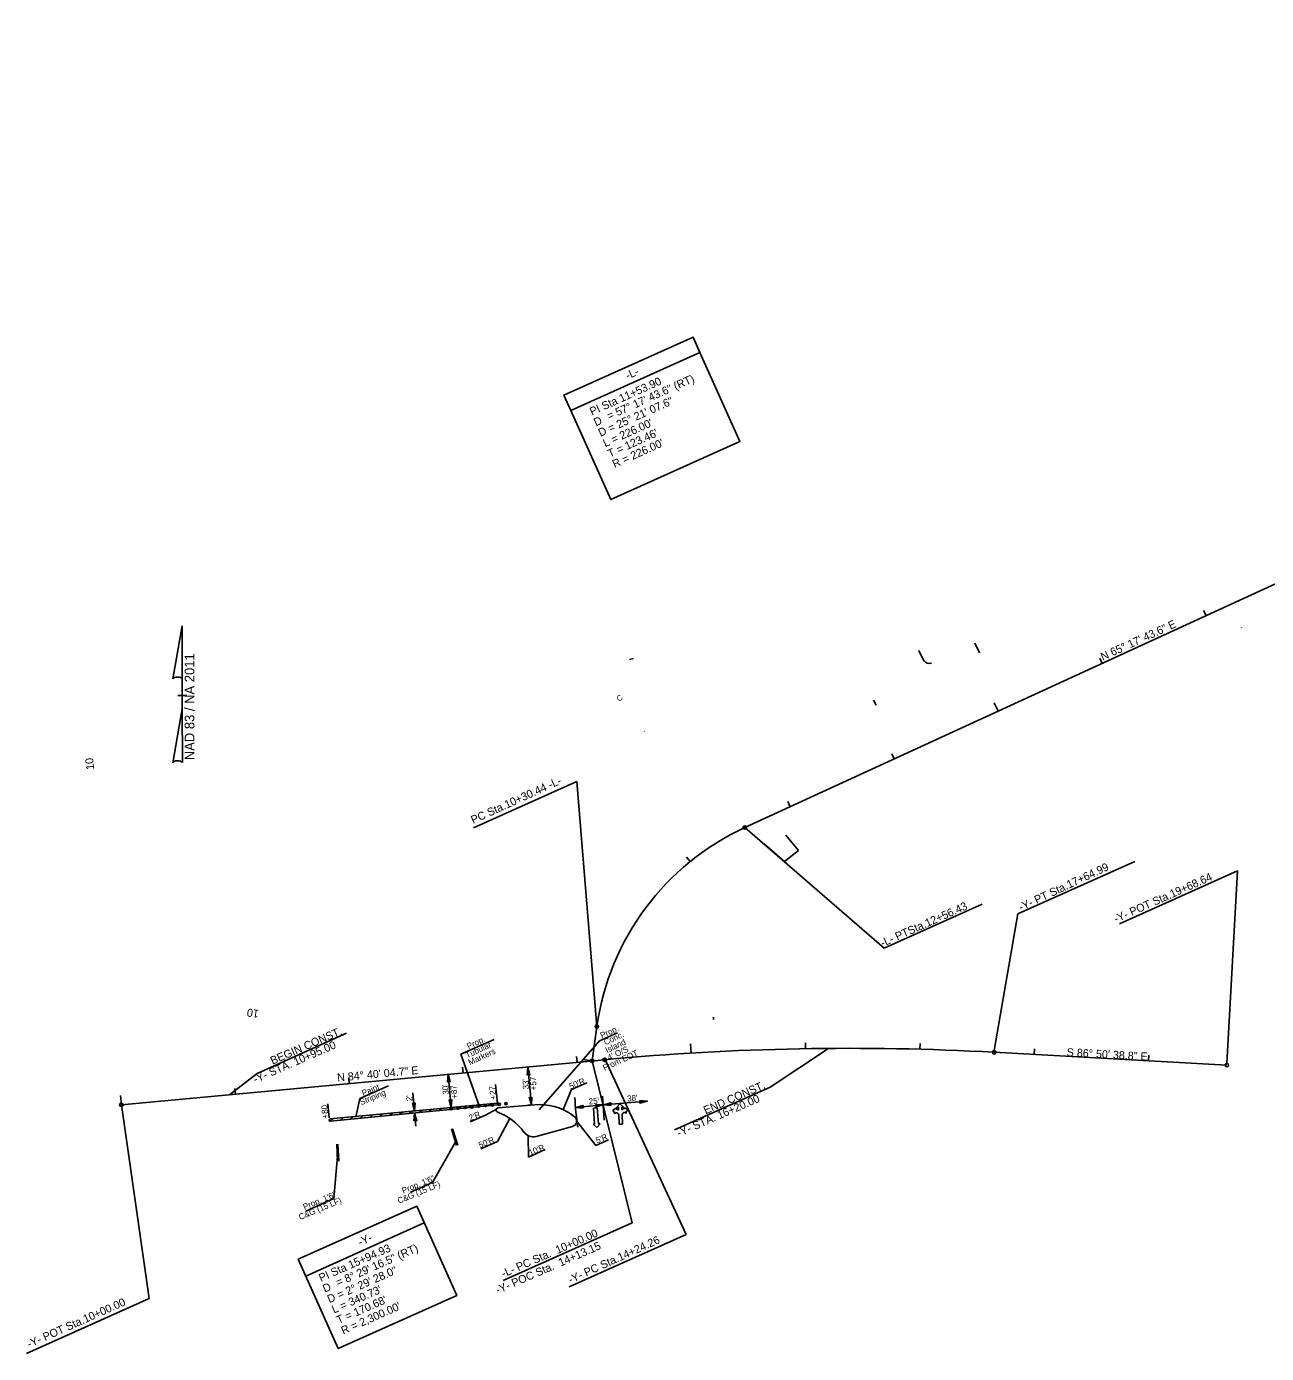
# Model space of a CAD drawing. Extents: x 549330 to 561351, y 501561 to 509732.
# Drawn here: x 553991 to 555075, y 502823 to 503983 of the extents above; entities that cross this region are included whole.
import ezdxf

# ---------------------------------------------------------------- set-up
doc = ezdxf.new("R2010")
doc.units = 0
for name, color, linetype in [('Old_Level_10', 7, 'Continuous'), ('Prop CMT Slope Fill', 7, 'Continuous'), ('Prop Conc 1ft 6in Curb and Gutter', 7, 'Continuous'), ('Prop Conc 5in Monolithic Surface Mount Island', 7, 'Continuous'), ('Prop Dimension', 7, 'Continuous'), ('Prop Drainage Structure Drop Inlet Grate 2 Narrow Slots and Flat Grates 840 29 TB CELL', 7, 'Continuous'), ('Prop Drainage Structure Pipe Alternate 15in', 7, 'Continuous'), ('Prop Drainage Structure Plot Symbol 50 Scale', 7, 'Continuous'), ('Prop Drainage Structure Tops and Inverts LABEL', 7, 'Continuous'), ('Prop Horizontal Alignment', 7, 'Continuous'), ('Prop Horizontal Alignment Station Label', 7, 'Continuous'), ('Prop Paint Stripe', 7, 'Continuous'), ('Prop Plan Preparation Table Ditch Data CELL', 7, 'Continuous'), ('Prop Shade Light', 7, 'Continuous'), ('Prop Shade Medium', 7, 'Continuous'), ('Prop SS Cut Text', 7, 'Continuous'), ('Scratch_Level_5', 7, 'Continuous'), ('Sheet Cutting Line CELL', 7, 'Continuous'), ('Sheet Sticker Incomplete CELL', 7, 'Continuous'), ('Sheet Title CELL', 7, 'Continuous'), ('Typical Terminator CELL', 7, 'Continuous')]:
    doc.layers.add(name, color=color, linetype=linetype)

msp = doc.modelspace()

# ---------------------------------------------------------------- linework, layer by layer
at = {"layer": 'Old_Level_10'}
for centre in [(554374.6, 503038.2), (554380.6, 503038.7), (554386.5, 503039.3), (554392.5, 503039.9), (554398.5, 503040.4), (554404.5, 503041), (554410.4, 503041.5), (554362.6, 503037.1), (554368.6, 503037.6)]:
    msp.add_circle(centre, 1, dxfattribs=at)
at = {"layer": 'Prop CMT Slope Fill'}
for p, q in [((554518.3, 503429.8), (554521.8, 503430.7)), ((554531.1, 503367.3), (554531.5, 503366.8))]:
    msp.add_line(p, q, dxfattribs=at)
at = {"layer": 'Prop Conc 1ft 6in Curb and Gutter'}
for p, q in [((554362.8, 503019.5), (554367.3, 503004.9)), ((554363.8, 503019.6), (554368.3, 503005.1)), ((554262.6, 503006.1), (554263.2, 502991.1)), ((554263.6, 503006.2), (554264.2, 502991.1))]:
    msp.add_line(p, q, dxfattribs=at)
at = {"layer": 'Prop Conc 5in Monolithic Surface Mount Island'}
for p, q in [((554403, 503040.8), (554403, 503040.8)), ((554403, 503040.8), (554403, 503040.8)), ((554403, 503040.8), (554403, 503040.8)), ((554403, 503040.8), (554403, 503040.8)), ((554403, 503040.8), (554403, 503040.8)), ((554403, 503040.8), (554403, 503040.8)), ((554403.7, 503037.9), (554435.2, 503040.6)), ((554468.1, 503031.8), (554470.1, 503030.4)), ((554436.9, 503012.9), (554468.6, 503021.5)), ((554436.9, 503012.9), (554468.6, 503021.5))]:
    msp.add_line(p, q, dxfattribs=at)
msp.add_lwpolyline([(554360.7, 503037.2), (554360.7, 503037.2)], dxfattribs=at)
for centre, radius, start, end in [((554439.5, 502990.8), 50, 55.0742, 94.9315), ((554403.9, 503035.9), 2, 94.9315, 249.5992), ((554385.7, 502987.2), 50, 36.037, 69.5992), ((554467.2, 503026.3), 5, 285.283, 55.0742), ((554434.3, 503022.5), 10, 216.037, 285.283)]:
    msp.add_arc(centre, radius, start, end, dxfattribs=at)
at = {"layer": 'Prop Dimension'}
for points in [[(554467, 503647.7), (554579.9, 503698.4), (554573.9, 503711.8), (554461, 503661.1)], [(554467, 503647.7), (554579.9, 503698.4), (554614.9, 503620.4), (554502, 503569.7)], [(554228.8, 502905.4), (554332.4, 502951.8), (554367.4, 502873.8), (554263.9, 502827.4)]]:
    msp.add_lwpolyline(points, close=True, dxfattribs=at)
at = {"layer": 'Prop Drainage Structure Drop Inlet Grate 2 Narrow Slots and Flat Grates 840 29 TB CELL'}
for points in [[(554359.3, 503060.4), (554359.8, 503067.3), (554361.6, 503060.6), (554360.4, 503061.4)], [(554429, 503066.4), (554429.5, 503073.2), (554431.4, 503066.6), (554430.1, 503067.3)], [(554331, 503042.1), (554330.4, 503035.3), (554328.6, 503041.9), (554329.9, 503041.2)], [(554363.1, 503045), (554362.5, 503038.2), (554360.7, 503044.8), (554362, 503044.1)], [(554433, 503047.3), (554432.6, 503040.4), (554430.7, 503047), (554431.9, 503046.3)], [(554478, 503037.6), (554471.2, 503038.2), (554477.8, 503040), (554477.1, 503038.7)], [(554488.7, 503040.9), (554495.5, 503040.4), (554488.9, 503038.6), (554489.6, 503039.8)], [(554502.3, 503039.8), (554495.5, 503040.4), (554502.2, 503042.2), (554501.4, 503040.9)], [(554527.1, 503044.4), (554533.9, 503043.8), (554527.3, 503042), (554528, 503043.3)], [(554330, 503026.5), (554330.6, 503033.3), (554332.4, 503026.6), (554331.1, 503027.4)]]:
    msp.add_lwpolyline(points, close=True, dxfattribs=at)
at = {"layer": 'Prop Drainage Structure Pipe Alternate 15in'}
msp.add_line((554591.7, 503117.2), (554591.8, 503115.2), dxfattribs=at)
at = {"layer": 'Prop Drainage Structure Plot Symbol 50 Scale'}
for p, q in [((554492.1, 503096.4), (554439.4, 503036.2)), ((554507.4, 503038.3), (554510, 503041.3)), ((554510, 503041.3), (554513, 503038.5)), ((554486.8, 503037.6), (554490.1, 503037.8)), ((554487.9, 503023.6), (554486.8, 503037.6)), ((554490.1, 503037.8), (554491.2, 503023.9)), ((554503.8, 503035.9), (554507.2, 503038)), ((554505.8, 503032.5), (554503.8, 503035.9)), ((554506.2, 503033.8), (554505.8, 503032.5)), ((554507.2, 503038), (554506.8, 503036.7)), ((554508.7, 503038.3), (554507.4, 503038.3)), ((554508.8, 503035.9), (554508.7, 503038.3)), ((554509.2, 503023.6), (554508.9, 503031.9)), ((554513, 503038.5), (554511.7, 503038.5)), ((554511.7, 503038.5), (554511.8, 503035.9)), ((554511.9, 503031.9), (554512.2, 503023.7)), ((554513.6, 503037), (554513.2, 503038.2)), ((554513.2, 503038.2), (554516.8, 503036.3)), ((554514.9, 503032.9), (554514.5, 503034.1)), ((554516.8, 503036.3), (554514.9, 503032.9)), ((554486.5, 503023.5), (554487.9, 503023.6)), ((554489.9, 503020.6), (554486.5, 503023.5)), ((554492.7, 503024), (554489.9, 503020.6)), ((554491.2, 503023.9), (554492.7, 503024)), ((554512.2, 503023.7), (554509.2, 503023.6)), ((554346.1, 502972.7), (554366.7, 503008.3)), ((554260.1, 502958.7), (554263.1, 502995.5)), ((554326.9, 502964.1), (554346.1, 502972.7)), ((554235.6, 502947.5), (554260.1, 502958.7))]:
    msp.add_line(p, q, dxfattribs=at)
for centre, radius, start, end in [((554505.5, 503029.9), 4, 49.4504, 80.663), ((554506.2, 503032.8), 4, 50.2568, 81.0333), ((554506.8, 503031.1), 2.28, 19.9425, 52.9405), ((554514.6, 503033.1), 4, 103.2775, 134.1672), ((554514.1, 503031.4), 2.28, 131.0867, 165.8528), ((554515.4, 503030.2), 4, 103.6467, 134.5768)]:
    msp.add_arc(centre, radius, start, end, dxfattribs=at)
at = {"layer": 'Prop Drainage Structure Tops and Inverts LABEL'}
for p, q in [((554371, 503084.8), (554400, 503097.7)), ((554492.1, 503096.4), (554508, 503103.5)), ((554371, 503084.8), (554386.9, 503039.5)), ((554359.8, 503067.3), (554362.5, 503038.2)), ((554429.5, 503073.7), (554432.6, 503040.4)), ((554282.7, 503045.9), (554307.7, 503057.1)), ((554328.9, 503051), (554330.4, 503035.3)), ((554401.4, 503058.3), (554402.9, 503041.8)), ((554467.7, 503053.8), (554460.5, 503036.5)), ((554467.7, 503053.8), (554481, 503059.7)), ((554254.7, 503041.4), (554255.9, 503029)), ((554282.7, 503045.9), (554279.1, 503029.6)), ((554471.2, 503038.2), (554495.5, 503040.4)), ((554495.5, 503040.4), (554533.9, 503043.8)), ((554330.6, 503033.3), (554331.6, 503021.9)), ((554379.2, 503025.6), (554392.6, 503031.5)), ((554392.6, 503031.5), (554402, 503036.6)), ((554402.9, 503008.4), (554413.8, 503028.6)), ((554488.9, 503005), (554472.1, 503026.4)), ((554388.4, 503001.9), (554402.9, 503008.4)), ((554430, 502994.8), (554429.9, 503013.3)), ((554488.9, 503005), (554500, 503010)), ((554430, 502994.8), (554444.6, 503001.3))]:
    msp.add_line(p, q, dxfattribs=at)
at = {"layer": 'Prop Horizontal Alignment Station Label'}
for p, q in [((554840.5, 503384.7), (554837.2, 503392)), ((554572.2, 503085.7), (554571.8, 503093.7)), ((554485.7, 503078.9), (554477.7, 503080)), ((554074.3, 503040.5), (554073.6, 503048.5))]:
    msp.add_line(p, q, dxfattribs=at)
at = {"layer": 'Prop Paint Stripe'}
for p, q in [((554256.8, 503028.1), (554402.9, 503041.8)), ((554257, 503026.1), (554403.1, 503040.4)), ((554377.6, 503037.9), (554379.8, 503039.8)), ((554386.3, 503038.7), (554388.5, 503040.6)), ((554394.9, 503039.6), (554396.9, 503041.3)), ((554402.9, 503041.8), (554403, 503040.4)), ((554256.8, 503026.1), (554259.4, 503028.4)), ((554265.4, 503026.9), (554268, 503029.2)), ((554274, 503027.8), (554276.7, 503030)), ((554282.7, 503028.6), (554285.3, 503030.8)), ((554291.3, 503029.4), (554293.9, 503031.7)), ((554299.9, 503030.3), (554302.5, 503032.5)), ((554308.6, 503031.1), (554311.1, 503033.3)), ((554317.2, 503032), (554319.7, 503034.1)), ((554325.8, 503032.8), (554328.3, 503034.9)), ((554334.5, 503033.7), (554337.1, 503035.9)), ((554343.1, 503034.5), (554345.5, 503036.6)), ((554351.7, 503035.3), (554354.1, 503037.4)), ((554360.4, 503036.2), (554362.7, 503038.2)), ((554362.7, 503036.4), (554362.5, 503038.2)), ((554369, 503037), (554371.3, 503039))]:
    msp.add_line(p, q, dxfattribs=at)
msp.add_arc((554256.9, 503027.1), 1, 96.6974, 274.0259, dxfattribs=at)
at = {"layer": 'Prop Plan Preparation Table Ditch Data CELL'}
msp.add_line((554494.9, 503048.2), (554496.2, 503027.1), dxfattribs=at)
msp.add_arc((554789.6, 503066.9), 319.7, 183.5862, 188.2689, dxfattribs=at)
at = {"layer": 'Prop Shade Light'}
msp.add_line((555053.5, 503457.9), (555053.1, 503457.7), dxfattribs=at)
at = {"layer": 'Prop Shade Medium'}
for p, q in [((554435.2, 503040.6), (554403.7, 503037.9)), ((554429.9, 503040.2), (554435.2, 503040.6)), ((554468.1, 503031.8), (554470.1, 503030.4)), ((554470.1, 503030.4), (554468.1, 503031.8)), ((554436.9, 503012.9), (554468.6, 503021.5))]:
    msp.add_line(p, q, dxfattribs=at)
for centre, radius, start, end in [((554439.5, 502990.8), 50, 55.0742, 94.9315), ((554439.5, 502990.8), 50, 55.0742, 94.9315), ((554403.9, 503035.9), 2, 94.9315, 249.5992), ((554385.7, 502987.2), 50, 36.037, 69.5992), ((554467.2, 503026.3), 5, 285.283, 55.0742), ((554467.2, 503026.3), 5, 285.283, 55.0742), ((554434.3, 503022.5), 10, 216.037, 285.283), ((554434.3, 503022.5), 10, 245.6162, 285.283)]:
    msp.add_arc(centre, radius, start, end, dxfattribs=at)
at = {"layer": 'Scratch_Level_5'}
for p, q in [((554775.7, 503428.8), (554771.2, 503437.8)), ((554820.1, 503444.2), (554824.2, 503435.8)), ((554654.9, 503276.2), (554666.1, 503262.8)), ((554636.4, 503268.3), (554653.9, 503253.2)), ((554636.7, 503267.9), (554655.2, 503251.7)), ((554653.9, 503253.2), (554666.1, 503262.8)), ((554383.3, 503100.9), (554383.3, 503100.9))]:
    msp.add_line(p, q, dxfattribs=at)
msp.add_arc((554780.1, 503431.3), 5, 209.4176, 295.0264, dxfattribs=at)
at = {"layer": 'Sheet Cutting Line CELL'}
for p, q in [((554619.2, 503282.9), (556141.7, 503983.3)), ((554485.7, 503078.9), (554489.9, 503109)), ((554837.1, 503086.4), (555040.4, 503075.2)), ((554074.3, 503040.5), (554496.7, 503079.9))]:
    msp.add_line(p, q, dxfattribs=at)
for centre, radius, start, end in [((554713.7, 503077.6), 226, 114.7046, 172), ((554710.5, 500789.9), 2300, 86.8441, 95.332)]:
    msp.add_arc(centre, radius, start, end, dxfattribs=at)
at = {"layer": 'Sheet Title CELL'}
for p, q in [((555022.2, 503468.3), (555020.1, 503472.8)), ((554931.4, 503426.5), (554929.3, 503431)), ((554731.5, 503394.4), (554733.8, 503389.9)), ((554749.7, 503342.9), (554747.6, 503347.4)), ((554658.8, 503301.1), (554656.7, 503305.7)), ((554571.4, 503253.2), (554568.3, 503257.1)), ((554672.2, 503089.6), (554672.1, 503094.6)), ((554772.2, 503089.1), (554772.3, 503094.1)), ((554872, 503084.5), (554872.3, 503089.5)), ((554472.6, 503077.7), (554472.1, 503082.7)), ((554971.9, 503079), (554972.2, 503084)), ((554273.4, 503059.1), (554273, 503064.1)), ((554373, 503068.4), (554372.5, 503073.4)), ((554173.9, 503049.8), (554173.4, 503054.8))]:
    msp.add_line(p, q, dxfattribs=at)
at = {"layer": 'Typical Terminator CELL'}
for p, q in [((554119.3, 503413.1), (554127.5, 503459.4)), ((554127.5, 503459.4), (554127.5, 503459.4)), ((554127.5, 503459.4), (554127.5, 503459.4)), ((554127.5, 503459.4), (554127.5, 503411.6)), ((554127.5, 503386.8), (554127.5, 503413)), ((554127.5, 503411.6), (554127.5, 503413)), ((554127.1, 503398.4), (554123.5, 503398.4)), ((554123.5, 503398.4), (554123.5, 503398.4)), ((554123.6, 503398.4), (554131.6, 503398.4)), ((554127.5, 503386.8), (554119.2, 503339.6)), ((554127.6, 503339.8), (554127.5, 503386.8)), ((554382.1, 503282.6), (554472.3, 503323.1)), ((554472.3, 503323.1), (554489.9, 503109)), ((554619.2, 503282.9), (554740.9, 503177.5)), ((554960, 503253.3), (554857.8, 503207.4)), ((555049.8, 503245), (554946.5, 503198.6)), ((555040.5, 503076.7), (555049.8, 503245)), ((554826.6, 503216), (554740.9, 503177.5)), ((554837.2, 503087.9), (554857.8, 503207.4)), ((554271, 503103), (554193, 503067.8)), ((554641.4, 503056), (554692.2, 503089.8)), ((554520.7, 502937.4), (554485.7, 503078.9)), ((554496.6, 503081.4), (554567.8, 502927.2)), ((554193, 503067.8), (554168.9, 503049.3)), ((554641.4, 503056), (554557.8, 503018.6)), ((554074.3, 503040.5), (554098.6, 502871.2)), ((554338.9, 502937.2), (554235.4, 502890.7)), ((554408.1, 502886.8), (554520.7, 502937.4)), ((554465.7, 502881.4), (554567.8, 502927.2)), ((553991.4, 502823.1), (554098.6, 502871.2))]:
    msp.add_line(p, q, dxfattribs=at)
for centre in [(554619.2, 503282.9), (554489.9, 503109), (554837.1, 503086.4), (554485.7, 503078.9), (554496.7, 503079.9), (555040.4, 503075.2), (554074.3, 503040.5)]:
    msp.add_circle(centre, 1.5, dxfattribs=at)
for centre, start_param, end_param in [((554123.4, 503412.6), 0.216388, 2.908219), ((554123.4, 503339.4), 0.201328, 3.141593)]:
    msp.add_ellipse(centre, major_axis=(4.23, -0.03), ratio=0.461098, start_param=start_param, end_param=end_param, dxfattribs=at)

# ---------------------------------------------------------------- texts
at = {"layer": 'Prop Dimension'}
for s, rotation, p in [('= 57%%d 17\' 43.6" (RT)', 24.1816, (554500.6, 503639.2)), ('-L-', 24.1816, (554516.8, 503674.6)), ('PI Sta 11+53.90', 24.1816, (554485.5, 503643.1)), ('D = 25%%d 21\' 07.6"', 24.1816, (554493, 503624.6)), ('D', 24.1816, (554489, 503633.7)), ("L = 226.00'", 24.1816, (554497.1, 503615.4)), ("T = 123.46'", 24.1816, (554501.2, 503606.3)), ("R = 226.00'", 24.1816, (554505.3, 503597.2)), ('-Y-', 24.1816, (554283, 502916.8)), ('PI Sta 15+94.93', 23.715, (554248.7, 502885.6)), ('= 8%%d 29\' 16.5" (RT)', 23.715, (554263.7, 502881.6)), ('D = 2%%d 29\' 28.0"', 23.715, (554256.1, 502867)), ('D', 23.715, (554252.1, 502876.2)), ("L = 340.73'", 23.715, (554260.1, 502857.9)), ("T = 170.68'", 23.715, (554264.1, 502848.7)), ("R = 2,300.00'", 23.715, (554268.2, 502839.5))]:
    msp.add_text(s, height=7, rotation=rotation, dxfattribs=at).set_placement(p)
at = {"layer": 'Prop Drainage Structure Plot Symbol 50 Scale'}
for s, rotation, p in [('Prop.', 24.9287, (554377.7, 503089)), ('Prop.', 24.9287, (554494.3, 503098.4)), ('Conc.', 24.9287, (554497.4, 503092.5)), ('Island', 24.9287, (554498.7, 503085.7)), ('Tubular', 24.9287, (554376.5, 503081.1)), ('Markers', 24.9287, (554378.9, 503074.9)), ('From EOT', 24.9287, (554496.6, 503070.1)), ("4' O/S ", 24.9287, (554500.5, 503079.2)), ("33'", 93.1358, (554430.5, 503054.1)), ('+57', 93.1358, (554437.2, 503053.3)), ("50'R", 22.6728, (554466.9, 503053.9)), ('Striping', 22.6728, (554284, 503040.1)), ('Paint', 22.6728, (554285.7, 503048)), ("30'", 95.0412, (554360.6, 503049.6)), ('+87', 95.0412, (554368.1, 503046)), ('+27', 95.0851, (554402, 503045.3)), ('+80', 95.0412, (554255.2, 503028.7)), ("2'", 95.0851, (554328.7, 503043.9)), ("25'", 4.7606, (554482.9, 503040.8)), ("38'", 4.7606, (554516.5, 503043.3)), ("2'R", 22.6728, (554379.2, 503026.3)), ("50'R", 22.6728, (554387.7, 503002.5)), ("10'R", 22.6728, (554431.7, 502995.9)), ("5'R", 22.6728, (554490.2, 503006.6)), ('C&G (15 LF)', 22.6728, (554316.9, 502953.9)), ('Prop. 1\'6" ', 22.6728, (554320.7, 502962.7)), ('C&G (15 LF)', 22.6728, (554230.6, 502939.7)), ('Prop. 1\'6" ', 22.6728, (554234.4, 502948.5))]:
    msp.add_text(s, height=5.25, rotation=rotation, dxfattribs=at).set_placement(p)
at = {"layer": 'Prop Horizontal Alignment'}
for rotation, p in [(95.332, (554050.5, 503333.7)), (172, (554194.9, 503123.3))]:
    msp.add_text('10', height=7, rotation=rotation, dxfattribs=at).set_placement(p)
at = {"layer": 'Prop SS Cut Text'}
msp.add_text('C', height=5, rotation=31.9629, dxfattribs=at).set_placement((554508.9, 503392.9))
at = {"layer": 'Sheet Sticker Incomplete CELL'}
for s, rotation, p in [('N 65%%d 17\' 43.6" E', 24.7046, (554932, 503428.7)), ('S 86%%d 50\' 38.8" E', 356.8441, (554900.3, 503083.1)), ('N 84%%d 40\' 04.7" E', 5.332, (554263.2, 503060.8))]:
    msp.add_text(s, height=7, rotation=rotation, dxfattribs=at).set_placement(p)
at = {"layer": 'Typical Terminator CELL'}
for s, height, rotation, p in [('NAD 83 / NA 2011', 8.5, 90, (554138.1, 503341.8)), ('PC Sta.10+30.44 -L-', 7, 24.5197, (554381.7, 503286)), ('-Y- PT Sta.17+64.99', 7, 25.177, (554860.5, 503209.7)), ('-Y- POT Sta.19+68.64', 7, 24.0019, (554943.5, 503199.5)), ('-L- PTSta.12+56.43', 7, 24.0837, (554739.6, 503178.4)), ('BEGIN CONST.', 7, 23.6123, (554206.4, 503075.5)), ('-Y- STA. 10+95.00', 7, 23.6123, (554191.3, 503059.2)), ('END CONST.', 7, 23.6123, (554584.9, 503032.1)), ('-Y- STA. 16+20.00', 7, 23.6123, (554561.6, 503012.3)), ('-L- PC Sta.  10+00.00', 7, 23.6123, (554408.3, 502889.4)), ('-Y- PC Sta.14+24.26', 7, 24.5061, (554466.8, 502884)), ('-Y- POC Sta.  14+13.15', 7, 23.6123, (554403.3, 502875)), ('-Y- POT Sta.10+00.00', 7, 23.9901, (553993.8, 502827.8))]:
    msp.add_text(s, height=height, rotation=rotation, dxfattribs=at).set_placement(p)

doc.saveas('drawing.dxf')
